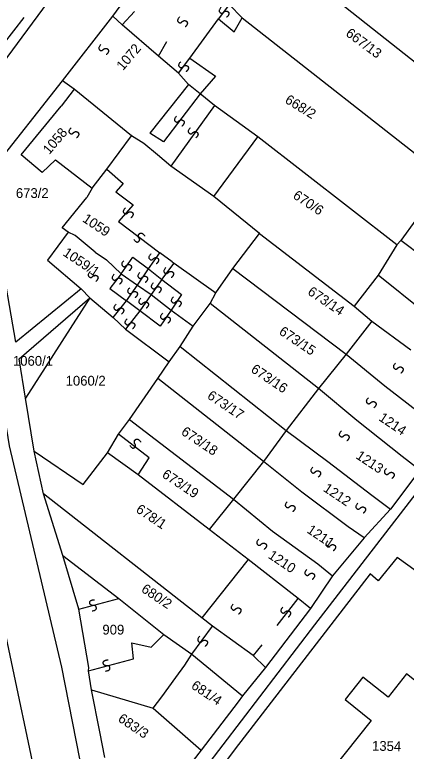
# Model space of a CAD drawing. Extents: x -581999 to -572728, y -1219553 to -1212032.
# Drawn here: x -577734.8 to -577654.8, y -1215045.8 to -1214895.3 of the extents above; entities that cross this region are included whole.
import ezdxf

# ---------------------------------------------------------------- set-up
doc = ezdxf.new("R2010")
doc.units = 0
for name, color, linetype in [('Vrstva 1', 7, 'Continuous'), ('Vrstva 2', 7, 'Continuous'), ('Vrstva 4', 7, 'Continuous'), ('Vrstva 6', 7, 'Continuous')]:
    doc.layers.add(name, color=color, linetype=linetype)

msp = doc.modelspace()

# ---------------------------------------------------------------- linework, layer by layer
at = {"layer": 'Vrstva 1'}
for p, q in [((-577705.462, -1214903.72), (-577712.842, -1214897.34)), ((-577725.096, -1214938.796), (-577720.086, -1214932.592)), ((-577723.874, -1214939.71), (-577725.096, -1214938.796)), ((-577722.467, -1214940.337), (-577723.874, -1214939.71)), ((-577718.342, -1214943.793), (-577722.467, -1214940.337)), ((-577631.381, -1214960.094), (-577655.945, -1214941.412)), ((-577636.913, -1214967.567), (-577660.593, -1214948.47)), ((-577709.739, -1214950.499), (-577706.929, -1214952.457)), ((-577719.452, -1214953.084), (-577714.678, -1214957.108)), ((-577623.323, -1214954.619), (-577673.556, -1215019.936)), ((-577687.146, -1215006.579), (-577696.562, -1215018.514)), ((-577676.9, -1215014.559), (-577677.542, -1215014.039)), ((-577674.357, -1215016.581), (-577676.9, -1215014.559)), ((-577673.556, -1215019.936), (-577711.491, -1215069.479))]:
    msp.add_line(p, q, dxfattribs=at)
for points in [[(-577714.791, -1214895.569), (-577705.058, -1214882.189), (-577696.075, -1214869.89), (-577694.087, -1214871.7)], [(-577726.097, -1214889.907), (-577737.394, -1214905.307)], [(-577672.441, -1214889.588), (-577638.078, -1214916.756), (-577639.86, -1214918.987)], [(-577691.016, -1214893.162), (-577688.368, -1214895.874)], [(-577725.038, -1214908.739), (-577714.791, -1214895.569)], [(-577714.791, -1214895.569), (-577712.842, -1214897.34)], [(-577699.016, -1214904.107), (-577693.207, -1214896.103)], [(-577693.207, -1214896.103), (-577689.998, -1214898.721), (-577688.368, -1214895.874)], [(-577688.368, -1214895.874), (-577646.983, -1214928.337)], [(-577701.376, -1214907.228), (-577705.462, -1214903.72)], [(-577699.016, -1214904.107), (-577693.796, -1214907.837), (-577696.96, -1214911.411)], [(-577699.279, -1214909.486), (-577701.376, -1214907.228)], [(-577721.217, -1214951.277), (-577734.554, -1214962.178), (-577739.113, -1214936.121), (-577739.514, -1214927.04), (-577725.038, -1214908.739)], [(-577722.668, -1214910.464), (-577725.038, -1214908.739)], [(-577696.96, -1214911.411), (-577699.279, -1214909.486)], [(-577722.668, -1214910.464), (-577725.335, -1214913.93)], [(-577710.956, -1214919.971), (-577722.668, -1214910.464)], [(-577693.978, -1214913.788), (-577696.96, -1214911.411)], [(-577726.484, -1214924.918), (-577729.194, -1214927.531), (-577733.507, -1214923.881), (-577725.335, -1214913.93)], [(-577685.164, -1214920.225), (-577693.978, -1214913.788)], [(-577725.151, -1215028.582), (-577735.904, -1214983.329), (-577746.549, -1214917.111)], [(-577715.964, -1214926.787), (-577710.956, -1214919.971)], [(-577708.414, -1214921.559), (-577710.956, -1214919.971)], [(-577694.164, -1214932.428), (-577685.164, -1214920.225)], [(-577656.786, -1214942.288), (-577685.164, -1214920.225)], [(-577705.653, -1214923.879), (-577708.414, -1214921.559)], [(-577702.892, -1214926.198), (-577705.653, -1214923.879)], [(-577726.484, -1214924.918), (-577718.971, -1214930.693)], [(-577694.164, -1214932.428), (-577702.892, -1214926.198)], [(-577718.971, -1214930.693), (-577715.964, -1214926.787)], [(-577718.971, -1214930.693), (-577720.086, -1214932.592)], [(-577684.777, -1214939.958), (-577694.164, -1214932.428)], [(-577652.889, -1214937.156), (-577655.945, -1214941.412), (-577656.786, -1214942.288)], [(-577723.874, -1214939.71), (-577728.132, -1214945.44), (-577721.217, -1214951.277)], [(-577690.234, -1214947.099), (-577684.777, -1214939.958)], [(-577684.777, -1214939.958), (-577665.49, -1214954.794)], [(-577656.786, -1214942.288), (-577660.593, -1214948.47), (-577665.49, -1214954.794)], [(-577718.342, -1214943.793), (-577716.089, -1214945.332)], [(-577716.089, -1214945.332), (-577713.091, -1214948.21)], [(-577694.914, -1214954.244), (-577693.728, -1214952.113), (-577690.234, -1214947.099)], [(-577690.234, -1214947.099), (-577667.071, -1214964.625)], [(-577713.091, -1214948.21), (-577709.739, -1214950.499)], [(-577721.217, -1214951.277), (-577719.452, -1214953.084)], [(-577732.602, -1214973.631), (-577733.902, -1214965.547), (-577719.452, -1214953.084)], [(-577719.452, -1214953.084), (-577732.602, -1214973.631)], [(-577706.929, -1214952.457), (-577702.855, -1214955.639), (-577698.366, -1214958.931)], [(-577698.366, -1214958.931), (-577694.914, -1214954.244)], [(-577672.763, -1214971.621), (-577694.914, -1214954.244)], [(-577665.49, -1214954.794), (-577661.848, -1214957.847)], [(-577714.678, -1214957.108), (-577712.207, -1214959.477), (-577703.262, -1214966.215)], [(-577661.848, -1214957.847), (-577667.071, -1214964.625)], [(-577661.848, -1214957.847), (-577653.899, -1214963.731)], [(-577701.041, -1214963.062), (-577698.366, -1214958.931)], [(-577705.591, -1214969.59), (-577703.262, -1214966.215), (-577701.041, -1214963.062)], [(-577701.041, -1214963.062), (-577679.331, -1214980.209)], [(-577667.071, -1214964.625), (-577672.763, -1214971.621)], [(-577667.071, -1214964.625), (-577659.236, -1214971.069)], [(-577711.383, -1214977.961), (-577705.591, -1214969.59)], [(-577684.007, -1214986.568), (-577705.591, -1214969.59)], [(-577659.236, -1214971.069), (-577649.635, -1214978.533)], [(-577672.763, -1214971.621), (-577679.331, -1214980.209)], [(-577664.927, -1214978.176), (-577672.763, -1214971.621)], [(-577730.87, -1214984.408), (-577732.602, -1214973.631)], [(-577723.919, -1215082.491), (-577736.309, -1215023.635), (-577745.87, -1214975.785)], [(-577713.611, -1214980.974), (-577711.383, -1214977.961)], [(-577711.383, -1214977.961), (-577690.087, -1214994.23)], [(-577655.657, -1214985.525), (-577664.927, -1214978.176)], [(-577679.331, -1214980.209), (-577684.007, -1214986.568)], [(-577679.331, -1214980.209), (-577670.83, -1214986.545)], [(-577715.84, -1214984.771), (-577713.611, -1214980.974)], [(-577730.87, -1214984.408), (-577720.849, -1214991.241), (-577715.84, -1214984.771)], [(-577728.909, -1214993.167), (-577730.87, -1214984.408)], [(-577709.561, -1214989.28), (-577715.84, -1214984.771)], [(-577652.066, -1214988.295), (-577655.657, -1214985.525)], [(-577684.007, -1214986.568), (-577690.087, -1214994.23)], [(-577676.17, -1214992.786), (-577684.007, -1214986.568)], [(-577670.83, -1214986.545), (-577661.889, -1214993.441)], [(-577695.095, -1215000.474), (-577709.561, -1214989.28)], [(-577652.066, -1214988.295), (-577658.077, -1214996.325)], [(-577724.967, -1215005.75), (-577728.909, -1214993.167)], [(-577683.594, -1215028.624), (-577686.132, -1215026.206), (-577694.384, -1215020.202), (-577696.562, -1215018.514), (-577728.909, -1214993.167)], [(-577666.676, -1214999.91), (-577676.17, -1214992.786)], [(-577661.889, -1214993.441), (-577658.077, -1214996.325)], [(-577690.087, -1214994.23), (-577695.095, -1215000.474)], [(-577690.087, -1214994.23), (-577682.14, -1215000.783)], [(-577658.077, -1214996.325), (-577663.415, -1215002.118)], [(-577663.415, -1215002.118), (-577666.676, -1214999.91)], [(-577687.146, -1215006.579), (-577695.095, -1215000.474)], [(-577682.14, -1215000.783), (-577672.866, -1215007.458)], [(-577663.415, -1215002.118), (-577669.868, -1215009.921)], [(-577721.686, -1215016.758), (-577724.967, -1215005.75)], [(-577724.967, -1215005.75), (-577713.51, -1215014.536)], [(-577677.542, -1215014.039), (-577687.146, -1215006.579)], [(-577672.866, -1215007.458), (-577669.868, -1215009.921)], [(-577468.366, -1215152.089), (-577468.704, -1215147.994), (-577523.492, -1215106.889), (-577562.025, -1215076.592), (-577603.116, -1215044.7), (-577656.7, -1215006.145), (-577660.535, -1215010.928), (-577662.179, -1215009.511)], [(-577662.179, -1215009.511), (-577689.755, -1215045.301), (-577707.587, -1215069.22)], [(-577669.868, -1215009.921), (-577674.357, -1215016.581)], [(-577713.51, -1215014.536), (-577704.347, -1215021.888)], [(-577674.357, -1215016.581), (-577683.594, -1215028.624)], [(-577719.74, -1215029.323), (-577719.701, -1215028.667), (-577721.686, -1215016.758)], [(-577704.347, -1215021.888), (-577698.618, -1215025.926)], [(-577701.908, -1215030.659), (-577700.066, -1215028.158), (-577698.618, -1215025.926)], [(-577698.618, -1215025.926), (-577688.267, -1215034.42)], [(-577701.896, -1215143.742), (-577714.827, -1215081.288), (-577725.151, -1215028.582)], [(-577683.594, -1215028.624), (-577688.267, -1215034.42)], [(-577719.108, -1215033.186), (-577719.74, -1215029.323)], [(-577635.968, -1215046.133), (-577634.205, -1215043.911), (-577639.06, -1215040.059), (-577640.196, -1215041.491), (-577654.761, -1215029.936), (-577658.528, -1215034.685), (-577663.667, -1215030.608)], [(-577704.743, -1215034.628), (-577701.908, -1215030.659)], [(-577663.667, -1215030.608), (-577667.319, -1215035.214), (-577661.98, -1215039.447), (-577672.596, -1215052.837), (-577655.293, -1215066.556), (-577656.248, -1215067.76), (-577651.177, -1215071.782), (-577646.036, -1215065.3), (-577648.509, -1215062.854)], [(-577719.108, -1215033.186), (-577706.523, -1215036.94)], [(-577717.402, -1215041.813), (-577719.108, -1215033.186)], [(-577706.523, -1215036.94), (-577704.743, -1215034.628)], [(-577688.267, -1215034.42), (-577689.158, -1215035.647), (-577696.726, -1215045.571)], [(-577706.523, -1215036.94), (-577696.726, -1215045.571)], [(-577716.433, -1215047.072), (-577717.402, -1215041.813)], [(-577696.726, -1215045.571), (-577705.764, -1215057.281), (-577712.59, -1215066.224)]]:
    msp.add_lwpolyline(points, dxfattribs=at)
at = {"layer": 'Vrstva 4'}
for p, q in [((-577704.388, -1214921.206), (-577707.217, -1214919.462)), ((-577702.63, -1214945.725), (-577705.171, -1214943.913)), ((-577707.455, -1214947.206), (-577704.782, -1214949.382)), ((-577704.782, -1214949.382), (-577702.271, -1214946.005)), ((-577704.782, -1214949.382), (-577706.929, -1214952.457)), ((-577704.782, -1214949.382), (-577700.768, -1214952.428)), ((-577706.929, -1214952.457), (-577709.285, -1214955.796)), ((-577700.768, -1214952.428), (-577702.855, -1214955.639)), ((-577714.678, -1214957.108), (-577711.967, -1214953.737)), ((-577709.285, -1214955.796), (-577711.967, -1214953.737)), ((-577709.285, -1214955.796), (-577712.207, -1214959.477)), ((-577705.11, -1214958.928), (-577709.285, -1214955.796)), ((-577702.855, -1214955.639), (-577705.11, -1214958.928)), ((-577681.227, -1215020.038), (-577676.9, -1215014.559)), ((-577698.618, -1215025.926), (-577694.384, -1215020.202)), ((-577684.333, -1215024.019), (-577686.132, -1215026.206))]:
    msp.add_line(p, q, dxfattribs=at)
for points in [[(-577691.016, -1214893.162), (-577693.207, -1214896.103)], [(-577710.313, -1214894.612), (-577712.842, -1214897.34)], [(-577732.932, -1214895.851), (-577737.198, -1214901.285)], [(-577705.462, -1214903.72), (-577703.752, -1214900.755)], [(-577701.376, -1214907.228), (-577699.016, -1214904.107)], [(-577699.279, -1214909.486), (-577707.217, -1214919.462)], [(-577696.96, -1214911.411), (-577704.388, -1214921.206)], [(-577693.978, -1214913.788), (-577702.892, -1214926.198)], [(-577715.964, -1214926.787), (-577712.644, -1214929.741)], [(-577712.644, -1214929.741), (-577714.155, -1214931.444), (-577710.591, -1214934.135), (-577713.609, -1214937.536)], [(-577713.609, -1214937.536), (-577705.171, -1214943.913)], [(-577707.455, -1214947.206), (-577705.171, -1214943.913)], [(-577713.091, -1214948.21), (-577710.712, -1214944.807), (-577707.455, -1214947.206)], [(-577702.63, -1214945.725), (-577702.271, -1214946.005), (-577693.728, -1214952.113)], [(-577709.739, -1214950.499), (-577707.455, -1214947.206)], [(-577713.091, -1214948.21), (-577715.349, -1214951.172)], [(-577715.349, -1214951.172), (-577711.967, -1214953.737)], [(-577711.967, -1214953.737), (-577709.739, -1214950.499)], [(-577709.561, -1214989.28), (-577707.339, -1214985.794), (-577713.611, -1214980.974)], [(-577721.686, -1215016.758), (-577713.51, -1215014.536)], [(-577706.953, -1215024.498), (-577704.347, -1215021.888)], [(-577719.74, -1215029.323), (-577710.546, -1215026.851), (-577710.905, -1215023.597), (-577706.953, -1215024.498)]]:
    msp.add_lwpolyline(points, dxfattribs=at)
at = {"layer": 'Vrstva 6'}
for points in [[(-577692.633, -1214893.732), (-577693.22, -1214894.354), (-577692.765, -1214894.963), (-577692.359, -1214894.951), (-577692.073, -1214894.646), (-577691.767, -1214894.492), (-577691.467, -1214894.508), (-577691.26, -1214894.61), (-577691.084, -1214894.813), (-577691.039, -1214895.177), (-577691.374, -1214895.689), (-577691.532, -1214895.781)], [(-577701.117, -1214895.694), (-577701.704, -1214896.316), (-577701.249, -1214896.925), (-577700.843, -1214896.913), (-577700.557, -1214896.608), (-577700.251, -1214896.454), (-577699.951, -1214896.47), (-577699.744, -1214896.572), (-577699.568, -1214896.775), (-577699.523, -1214897.139), (-577699.858, -1214897.651), (-577700.016, -1214897.743)], [(-577717.217, -1214901.365), (-577717.804, -1214901.987), (-577717.349, -1214902.596), (-577716.943, -1214902.584), (-577716.657, -1214902.279), (-577716.351, -1214902.125), (-577716.051, -1214902.141), (-577715.844, -1214902.243), (-577715.668, -1214902.446), (-577715.623, -1214902.81), (-577715.958, -1214903.322), (-577716.116, -1214903.414)], [(-577700.9, -1214904.855), (-577701.487, -1214905.477), (-577701.032, -1214906.086), (-577700.626, -1214906.074), (-577700.34, -1214905.769), (-577700.034, -1214905.615), (-577699.734, -1214905.631), (-577699.527, -1214905.733), (-577699.351, -1214905.936), (-577699.306, -1214906.3), (-577699.641, -1214906.812), (-577699.799, -1214906.904)], [(-577701.77, -1214915.978), (-577702.357, -1214916.6), (-577701.902, -1214917.209), (-577701.496, -1214917.197), (-577701.21, -1214916.892), (-577700.904, -1214916.738), (-577700.604, -1214916.754), (-577700.397, -1214916.856), (-577700.221, -1214917.059), (-577700.176, -1214917.423), (-577700.511, -1214917.935), (-577700.669, -1214918.027)], [(-577723.309, -1214918.377), (-577723.896, -1214918.999), (-577723.441, -1214919.608), (-577723.035, -1214919.596), (-577722.749, -1214919.291), (-577722.443, -1214919.137), (-577722.143, -1214919.153), (-577721.936, -1214919.255), (-577721.76, -1214919.458), (-577721.715, -1214919.822), (-577722.05, -1214920.334), (-577722.208, -1214920.426)], [(-577698.942, -1214918.377), (-577699.529, -1214918.999), (-577699.074, -1214919.608), (-577698.668, -1214919.596), (-577698.382, -1214919.291), (-577698.076, -1214919.137), (-577697.776, -1214919.153), (-577697.569, -1214919.255), (-577697.393, -1214919.458), (-577697.348, -1214919.822), (-577697.683, -1214920.334), (-577697.841, -1214920.426)], [(-577712.213, -1214934.734), (-577712.8, -1214935.356), (-577712.345, -1214935.965), (-577711.939, -1214935.953), (-577711.653, -1214935.648), (-577711.347, -1214935.494), (-577711.047, -1214935.51), (-577710.84, -1214935.612), (-577710.664, -1214935.815), (-577710.619, -1214936.179), (-577710.954, -1214936.691), (-577711.112, -1214936.783)], [(-577710.506, -1214941.135), (-577710.026, -1214941.842), (-577709.332, -1214941.531), (-577709.255, -1214941.131), (-577709.491, -1214940.786), (-577709.576, -1214940.454), (-577709.494, -1214940.164), (-577709.35, -1214939.984), (-577709.114, -1214939.856), (-577708.749, -1214939.892), (-577708.322, -1214940.331), (-577708.267, -1214940.504)], [(-577706.984, -1214944.12), (-577707.571, -1214944.742), (-577707.116, -1214945.351), (-577706.71, -1214945.339), (-577706.424, -1214945.034), (-577706.118, -1214944.88), (-577705.818, -1214944.896), (-577705.611, -1214944.998), (-577705.435, -1214945.201), (-577705.39, -1214945.565), (-577705.725, -1214946.077), (-577705.883, -1214946.169)], [(-577712.536, -1214945.527), (-577713.123, -1214946.149), (-577712.668, -1214946.758), (-577712.262, -1214946.746), (-577711.976, -1214946.441), (-577711.67, -1214946.287), (-577711.37, -1214946.303), (-577711.163, -1214946.405), (-577710.987, -1214946.608), (-577710.942, -1214946.972), (-577711.277, -1214947.484), (-577711.435, -1214947.576)], [(-577703.933, -1214946.935), (-577704.52, -1214947.557), (-577704.065, -1214948.166), (-577703.659, -1214948.154), (-577703.373, -1214947.849), (-577703.067, -1214947.695), (-577702.767, -1214947.711), (-577702.56, -1214947.813), (-577702.384, -1214948.016), (-577702.339, -1214948.38), (-577702.674, -1214948.892), (-577702.832, -1214948.984)], [(-577719.37, -1214947.73), (-577719.957, -1214948.352), (-577719.502, -1214948.961), (-577719.096, -1214948.949), (-577718.81, -1214948.644), (-577718.504, -1214948.49), (-577718.204, -1214948.506), (-577717.997, -1214948.608), (-577717.821, -1214948.811), (-577717.776, -1214949.175), (-577718.111, -1214949.687), (-577718.269, -1214949.779)], [(-577714.489, -1214948.281), (-577715.076, -1214948.903), (-577714.621, -1214949.512), (-577714.215, -1214949.5), (-577713.929, -1214949.195), (-577713.623, -1214949.041), (-577713.323, -1214949.057), (-577713.116, -1214949.159), (-577712.94, -1214949.362), (-577712.895, -1214949.726), (-577713.23, -1214950.238), (-577713.388, -1214950.33)], [(-577709.241, -1214947.914), (-577709.828, -1214948.536), (-577709.373, -1214949.145), (-577708.967, -1214949.133), (-577708.681, -1214948.828), (-577708.375, -1214948.674), (-577708.075, -1214948.69), (-577707.868, -1214948.792), (-577707.692, -1214948.995), (-577707.647, -1214949.359), (-577707.982, -1214949.871), (-577708.14, -1214949.963)], [(-577706.496, -1214950.056), (-577707.083, -1214950.678), (-577706.628, -1214951.287), (-577706.222, -1214951.275), (-577705.936, -1214950.97), (-577705.63, -1214950.816), (-577705.33, -1214950.832), (-577705.123, -1214950.934), (-577704.947, -1214951.137), (-577704.902, -1214951.501), (-577705.237, -1214952.013), (-577705.395, -1214952.105)], [(-577711.316, -1214951.035), (-577711.903, -1214951.657), (-577711.448, -1214952.266), (-577711.042, -1214952.254), (-577710.756, -1214951.949), (-577710.45, -1214951.795), (-577710.15, -1214951.811), (-577709.943, -1214951.913), (-577709.767, -1214952.116), (-577709.722, -1214952.48), (-577710.057, -1214952.992), (-577710.215, -1214953.084)], [(-577709.058, -1214953.177), (-577709.645, -1214953.799), (-577709.19, -1214954.408), (-577708.784, -1214954.396), (-577708.498, -1214954.091), (-577708.192, -1214953.937), (-577707.892, -1214953.953), (-577707.685, -1214954.055), (-577707.509, -1214954.258), (-577707.464, -1214954.622), (-577707.799, -1214955.134), (-577707.957, -1214955.226)], [(-577702.408, -1214952.932), (-577702.995, -1214953.554), (-577702.54, -1214954.163), (-577702.134, -1214954.151), (-577701.848, -1214953.846), (-577701.542, -1214953.692), (-577701.242, -1214953.708), (-577701.035, -1214953.81), (-577700.859, -1214954.013), (-577700.814, -1214954.377), (-577701.149, -1214954.889), (-577701.307, -1214954.981)], [(-577714.123, -1214954.401), (-577714.71, -1214955.023), (-577714.255, -1214955.632), (-577713.849, -1214955.62), (-577713.563, -1214955.315), (-577713.257, -1214955.161), (-577712.957, -1214955.177), (-577712.75, -1214955.279), (-577712.574, -1214955.482), (-577712.529, -1214955.846), (-577712.864, -1214956.358), (-577713.022, -1214956.45)], [(-577704.604, -1214956.237), (-577705.191, -1214956.859), (-577704.736, -1214957.468), (-577704.33, -1214957.456), (-577704.044, -1214957.151), (-577703.738, -1214956.997), (-577703.438, -1214957.013), (-577703.231, -1214957.115), (-577703.055, -1214957.318), (-577703.01, -1214957.682), (-577703.345, -1214958.194), (-577703.503, -1214958.286)], [(-577711.865, -1214957.4), (-577712.452, -1214958.022), (-577711.997, -1214958.631), (-577711.591, -1214958.619), (-577711.305, -1214958.314), (-577710.999, -1214958.16), (-577710.699, -1214958.176), (-577710.492, -1214958.278), (-577710.316, -1214958.481), (-577710.271, -1214958.845), (-577710.606, -1214959.357), (-577710.764, -1214959.449)], [(-577657.041, -1214966.455), (-577657.628, -1214967.077), (-577657.173, -1214967.686), (-577656.767, -1214967.674), (-577656.481, -1214967.369), (-577656.175, -1214967.215), (-577655.875, -1214967.231), (-577655.668, -1214967.333), (-577655.492, -1214967.536), (-577655.447, -1214967.9), (-577655.782, -1214968.412), (-577655.94, -1214968.504)], [(-577662.563, -1214973.532), (-577663.15, -1214974.154), (-577662.695, -1214974.763), (-577662.289, -1214974.751), (-577662.003, -1214974.446), (-577661.697, -1214974.292), (-577661.397, -1214974.308), (-577661.19, -1214974.41), (-577661.014, -1214974.613), (-577660.969, -1214974.977), (-577661.304, -1214975.489), (-577661.462, -1214975.581)], [(-577668.084, -1214980.301), (-577668.671, -1214980.923), (-577668.216, -1214981.532), (-577667.81, -1214981.52), (-577667.524, -1214981.215), (-577667.218, -1214981.061), (-577666.918, -1214981.077), (-577666.711, -1214981.179), (-577666.535, -1214981.382), (-577666.49, -1214981.746), (-577666.825, -1214982.258), (-577666.983, -1214982.35)], [(-577711.325, -1214983.241), (-577710.845, -1214983.948), (-577710.151, -1214983.637), (-577710.074, -1214983.237), (-577710.31, -1214982.892), (-577710.395, -1214982.56), (-577710.313, -1214982.27), (-577710.169, -1214982.09), (-577709.933, -1214981.962), (-577709.568, -1214981.998), (-577709.141, -1214982.437), (-577709.086, -1214982.61)], [(-577673.913, -1214987.685), (-577674.5, -1214988.307), (-577674.045, -1214988.916), (-577673.639, -1214988.904), (-577673.353, -1214988.599), (-577673.047, -1214988.445), (-577672.747, -1214988.461), (-577672.54, -1214988.563), (-577672.364, -1214988.766), (-577672.319, -1214989.13), (-577672.654, -1214989.642), (-577672.812, -1214989.734)], [(-577658.881, -1214987.993), (-577659.468, -1214988.615), (-577659.013, -1214989.224), (-577658.607, -1214989.212), (-577658.321, -1214988.907), (-577658.015, -1214988.753), (-577657.715, -1214988.769), (-577657.508, -1214988.871), (-577657.332, -1214989.074), (-577657.287, -1214989.438), (-577657.622, -1214989.95), (-577657.78, -1214990.042)], [(-577679.127, -1214994.762), (-577679.714, -1214995.384), (-577679.259, -1214995.993), (-577678.853, -1214995.981), (-577678.567, -1214995.676), (-577678.261, -1214995.522), (-577677.961, -1214995.538), (-577677.754, -1214995.64), (-577677.578, -1214995.843), (-577677.533, -1214996.207), (-577677.868, -1214996.719), (-577678.026, -1214996.811)], [(-577664.71, -1214995.07), (-577665.297, -1214995.692), (-577664.842, -1214996.301), (-577664.436, -1214996.289), (-577664.15, -1214995.984), (-577663.844, -1214995.83), (-577663.544, -1214995.846), (-577663.337, -1214995.948), (-577663.161, -1214996.151), (-577663.116, -1214996.515), (-577663.451, -1214997.027), (-577663.609, -1214997.119)], [(-577684.956, -1215002.454), (-577685.543, -1215003.076), (-577685.088, -1215003.685), (-577684.682, -1215003.673), (-577684.396, -1215003.368), (-577684.09, -1215003.214), (-577683.79, -1215003.23), (-577683.583, -1215003.332), (-577683.407, -1215003.535), (-577683.362, -1215003.899), (-577683.697, -1215004.411), (-577683.855, -1215004.503)], [(-577670.845, -1215002.762), (-577671.432, -1215003.384), (-577670.977, -1215003.993), (-577670.571, -1215003.981), (-577670.285, -1215003.676), (-577669.979, -1215003.522), (-577669.679, -1215003.538), (-577669.472, -1215003.64), (-577669.296, -1215003.843), (-577669.251, -1215004.207), (-577669.586, -1215004.719), (-577669.744, -1215004.811)], [(-577675.14, -1215008.607), (-577675.727, -1215009.229), (-577675.272, -1215009.838), (-577674.866, -1215009.826), (-577674.58, -1215009.521), (-577674.274, -1215009.367), (-577673.974, -1215009.383), (-577673.767, -1215009.485), (-577673.591, -1215009.688), (-577673.546, -1215010.052), (-577673.881, -1215010.564), (-577674.039, -1215010.656)], [(-577719.013, -1215017.073), (-577718.162, -1215016.984), (-577718.11, -1215016.226), (-577718.426, -1215015.97), (-577718.842, -1215016.015), (-577719.174, -1215015.933), (-577719.391, -1215015.725), (-577719.482, -1215015.513), (-577719.483, -1215015.244), (-577719.28, -1215014.939), (-577718.692, -1215014.769), (-577718.512, -1215014.802)], [(-577690.171, -1215015.684), (-577690.758, -1215016.306), (-577690.303, -1215016.915), (-577689.897, -1215016.903), (-577689.611, -1215016.598), (-577689.305, -1215016.444), (-577689.005, -1215016.46), (-577688.798, -1215016.562), (-577688.622, -1215016.765), (-577688.577, -1215017.129), (-577688.912, -1215017.641), (-577689.07, -1215017.733)], [(-577680.048, -1215016.299), (-577680.635, -1215016.921), (-577680.18, -1215017.53), (-577679.774, -1215017.518), (-577679.488, -1215017.213), (-577679.182, -1215017.059), (-577678.882, -1215017.075), (-577678.675, -1215017.177), (-577678.499, -1215017.38), (-577678.454, -1215017.744), (-577678.789, -1215018.256), (-577678.947, -1215018.348)], [(-577697.014, -1215022.276), (-577697.601, -1215022.898), (-577697.146, -1215023.507), (-577696.74, -1215023.495), (-577696.454, -1215023.19), (-577696.148, -1215023.036), (-577695.848, -1215023.052), (-577695.641, -1215023.154), (-577695.465, -1215023.357), (-577695.42, -1215023.721), (-577695.755, -1215024.233), (-577695.913, -1215024.325)], [(-577716.253, -1215029.38), (-577715.402, -1215029.291), (-577715.35, -1215028.533), (-577715.666, -1215028.277), (-577716.082, -1215028.322), (-577716.414, -1215028.24), (-577716.631, -1215028.032), (-577716.722, -1215027.82), (-577716.723, -1215027.551), (-577716.52, -1215027.246), (-577715.932, -1215027.076), (-577715.752, -1215027.109)]]:
    msp.add_open_spline(points, degree=2, dxfattribs=at)

# ---------------------------------------------------------------- texts
at = {"layer": 'Vrstva 2'}
for s, rotation, p in [('667/13', 323.42903, (-577667.359, -1214899.416)), ('1072', 49.92375, (-577712.701, -1214906.797)), ('668/2', 328.50405, (-577679.771, -1214913.143)), ('1058', 49.92375, (-577727.744, -1214923.953)), ('670/6', 326.2453, (-577678.144, -1214932.632)), ('1059', 326.2453, (-577721.134, -1214937.399)), ('1059/1', 326.2453, (-577725.126, -1214944.337)), ('673/14', 326.2453, (-577675.137, -1214952.291)), ('673/15', 326.2453, (-577680.993, -1214960.432)), ('673/16', 326.2453, (-577686.732, -1214968.139)), ('673/17', 326.2453, (-577695.651, -1214973.535)), ('1214', 326.2453, (-577660.617, -1214978.034)), ('673/18', 326.2453, (-577700.979, -1214980.908)), ('1213', 326.2453, (-577665.28, -1214985.794)), ('673/19', 326.2453, (-577704.886, -1214989.628)), ('1212', 326.2453, (-577671.945, -1214992.491)), ('678/1', 326.2453, (-577710.214, -1214996.767)), ('1211', 326.2453, (-577675.293, -1215000.968)), ('1210', 326.2453, (-577683.216, -1215006.159)), ('680/2', 326.2453, (-577709.123, -1215013.054)), ('681/4', 326.2453, (-577698.922, -1215032.782)), ('683/3', 326.03923, (-577713.873, -1215039.531)), ('1354', 358.59094, (-577661.835, -1215045.624))]:
    msp.add_text(s, height=2, rotation=rotation, dxfattribs=at).set_placement(p)
for s, p in [('673/2', (-577734.568, -1214932.7)), ('1060/1', (-577735.171, -1214966.985)), ('1060/2', (-577724.407, -1214971.044)), ('909', (-577716.893, -1215021.914))]:
    msp.add_text(s, height=2, dxfattribs=at).set_placement(p)

doc.saveas('drawing.dxf')
